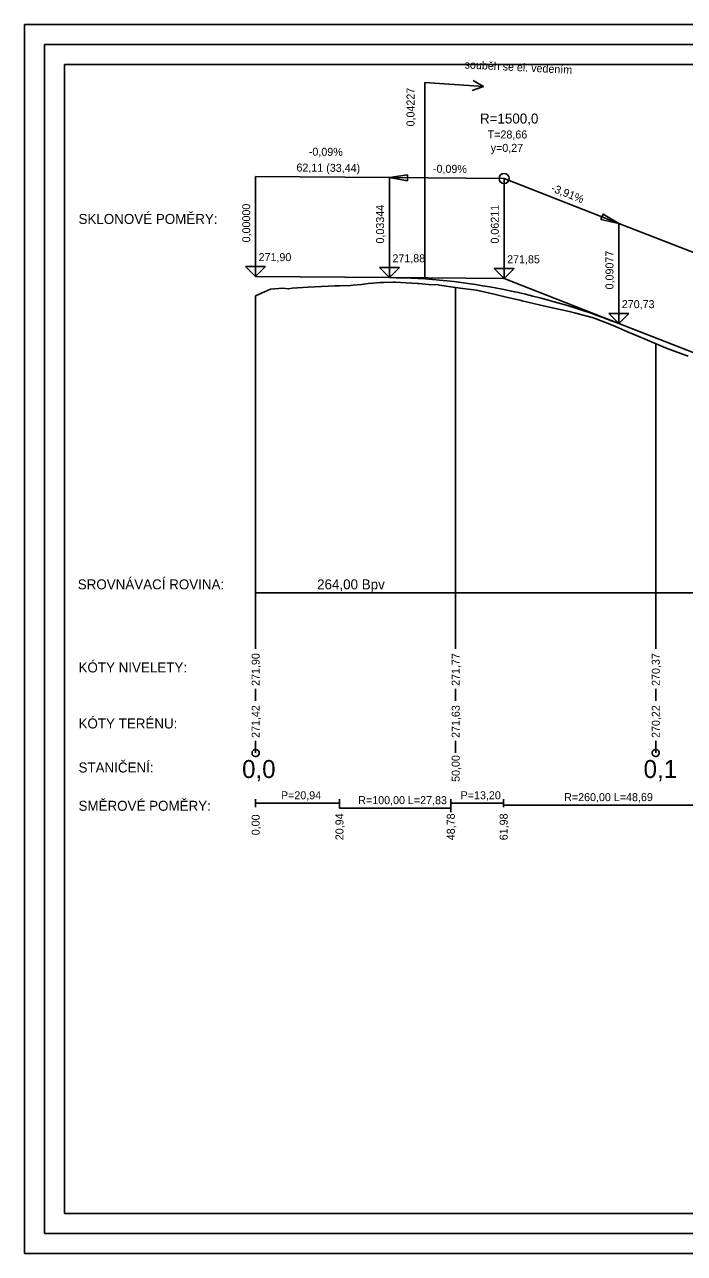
# Model space of a CAD drawing. Extents: x -762531 to -762101, y -1049246 to -1048939.
# Drawn here: x -762531.1 to -762366.2, y -1049246.4 to -1048939.4 of the extents above; entities that cross this region are included whole.
import ezdxf

# ---------------------------------------------------------------- set-up
doc = ezdxf.new("R2010")
doc.units = 0
for name, color, linetype in [('C3D-PROFIL-NIVELETA', 7, 'Continuous'), ('C3D-PROFIL-POPIS', 7, 'Continuous'), ('C3D-PROFIL-POPIS-NIVELETA', 7, 'Continuous'), ('C3D-PROFIL-TEREN', 7, 'Continuous'), ('C3D-ZOBPROF-OSY-NADPIS', 7, 'Continuous'), ('C3D-ZOBPROF-PROUZEK-NAVRH', 7, 'Continuous'), ('C3D-ZOBPROF-PROUZEK-POPIS', 7, 'Continuous'), ('C3D-ZOBPROF-PROUZEK-TEREN', 7, 'Continuous'), ('C3D-ZOBPROF-RASTR-VERHL', 7, 'Continuous'), ('C3D-ZOBPROF-RASTR-VERVEDL', 7, 'Continuous'), ('C3D-ZOBPROF-SROV-ROVINA', 7, 'Continuous'), ('Default', 7, 'Continuous'), ('krizeni_podelnak', 7, 'Continuous'), ('U_formát', 7, 'Continuous'), ('U_rozvržení_rámeček', 7, 'Continuous')]:
    doc.layers.add(name, color=color, linetype=linetype)

# ---------------------------------------------------------------- blocks, each defined once
blk = doc.blocks.new('PP-sipka')
at = {"layer": 'Default'}
for p, q in [((0, 0), (-4, 4)), ((-4, 4), (4, 4)), ((4, 4), (0, 0))]:
    blk.add_line(p, q, dxfattribs=at)
blk = doc.blocks.new('AeccTickCircle')
at = {"layer": 'Default'}
blk.add_circle((0, 0), 0.5, dxfattribs=at)
blk = doc.blocks.new('AeccArwClosedFilled')
at = {"layer": 'Default'}
blk.add_lwpolyline([(0.18, 0.03), (0.18, -0.03), (0, 0)], close=True, dxfattribs=at)
blk = doc.blocks.new('U1096')
at = {"layer": 'Default'}
for p, q in [((-420, 0), (-420, -10)), ((-420, -297), (-420, -287)), ((-420, -297), (-410, -297))]:
    blk.add_line(p, q, dxfattribs=at)
blk.add_lwpolyline([(0, -297), (0, 0), (-420, 0), (-420, -297)], close=True, dxfattribs=at)
at = {"layer": 'U_formát'}
for points in [[(-425, 5), (5, 5), (5, -302), (-425, -302)], [(-5, -292), (-5, -5), (-415, -5), (-415, -292)]]:
    blk.add_lwpolyline(points, close=True, dxfattribs=at)

msp = doc.modelspace()

# ---------------------------------------------------------------- linework, layer by layer
at = {"layer": 'C3D-PROFIL-NIVELETA'}
msp.add_lwpolyline([(-762473.38, -1049002.32), (-762439.93, -1049002.61), (-762438.14, -1049002.63), (-762436.35, -1049002.68), (-762434.56, -1049002.75), (-762432.77, -1049002.84), (-762430.98, -1049002.95), (-762429.19, -1049003.09), (-762427.39, -1049003.24), (-762425.6, -1049003.42), (-762423.81, -1049003.61), (-762422.02, -1049003.83), (-762420.23, -1049004.07), (-762418.44, -1049004.33), (-762416.64, -1049004.62), (-762414.85, -1049004.92), (-762413.06, -1049005.25), (-762411.27, -1049005.59), (-762409.48, -1049005.96), (-762407.69, -1049006.35), (-762405.9, -1049006.76), (-762404.1, -1049007.2), (-762402.31, -1049007.65), (-762400.52, -1049008.13), (-762398.73, -1049008.62), (-762396.94, -1049009.14), (-762395.15, -1049009.68), (-762393.35, -1049010.24), (-762391.56, -1049010.82), (-762389.77, -1049011.43), (-762387.98, -1049012.05), (-762386.19, -1049012.7), (-762384.4, -1049013.37), (-762382.61, -1049014.06), (-762323.08, -1049037.32)], dxfattribs=at)
at = {"layer": 'C3D-PROFIL-POPIS'}
msp.add_line((-762473.38, -1049007.18), (-762473.38, -1049081.36), dxfattribs=at)
at = {"layer": 'C3D-PROFIL-POPIS-NIVELETA'}
for p, q in [((-762473.38, -1049002.32), (-762473.38, -1048977.32)), ((-762473.38, -1048977.32), (-762439.93, -1048977.61)), ((-762439.93, -1049002.61), (-762439.93, -1048977.61)), ((-762439.93, -1048977.61), (-762411.27, -1048977.85)), ((-762439.93, -1049002.61), (-762439.93, -1048977.61)), ((-762411.27, -1049002.85), (-762411.27, -1048977.85)), ((-762411.27, -1048977.85), (-762382.61, -1048989.06)), ((-762382.61, -1049014.06), (-762382.61, -1048989.06)), ((-762382.61, -1049014.06), (-762382.61, -1048989.06)), ((-762382.61, -1048989.06), (-762323.08, -1049012.32)), ((-762411.27, -1049002.85), (-762439.93, -1049002.61)), ((-762411.27, -1049002.85), (-762382.61, -1049014.06))]:
    msp.add_line(p, q, dxfattribs=at)
at = {"layer": 'C3D-PROFIL-TEREN'}
msp.add_lwpolyline([(-762473.38, -1049007.18), (-762469.67, -1049005.49), (-762466.54, -1049005.26), (-762465.13, -1049005.44), (-762464.26, -1049005.27), (-762460.2, -1049004.95), (-762453.6, -1049004.64), (-762452.43, -1049004.62), (-762449.65, -1049004.55), (-762449.01, -1049004.53), (-762446.87, -1049004.29), (-762445.22, -1049004.09), (-762444.08, -1049004), (-762442.15, -1049003.83), (-762441.3, -1049003.8), (-762438.98, -1049003.71), (-762438.52, -1049003.74), (-762435.73, -1049003.93), (-762432.95, -1049004.1), (-762432.66, -1049004.11), (-762430.17, -1049004.29), (-762427.75, -1049004.44), (-762427.38, -1049004.49), (-762424.6, -1049004.9), (-762422.28, -1049005.23), (-762418.17, -1049005.77), (-762413.78, -1049006.75), (-762411.4, -1049007.29), (-762406.97, -1049008.31), (-762406.73, -1049008.37), (-762402.54, -1049009.37), (-762401.39, -1049009.64), (-762398.12, -1049010.38), (-762395.32, -1049011.01), (-762393.69, -1049011.44), (-762389.27, -1049012.59), (-762389.19, -1049012.61), (-762384.84, -1049014.26), (-762383.46, -1049014.79), (-762380.41, -1049016.12), (-762377.57, -1049017.35), (-762375.99, -1049018.02), (-762371.56, -1049019.87), (-762370.51, -1049020.31), (-762367.13, -1049021.57), (-762365.27, -1049022.26)], dxfattribs=at)
at = {"layer": 'C3D-ZOBPROF-PROUZEK-NAVRH'}
for p, q in [((-762473.38, -1049134.93), (-762473.38, -1049132.93)), ((-762473.38, -1049133.93), (-762452.43, -1049133.93)), ((-762452.43, -1049134.93), (-762452.43, -1049132.93)), ((-762452.43, -1049133.93), (-762452.43, -1049135.14)), ((-762452.43, -1049135.14), (-762424.6, -1049135.14)), ((-762424.6, -1049136.14), (-762424.6, -1049132.93)), ((-762424.6, -1049135.14), (-762424.6, -1049133.93)), ((-762424.6, -1049133.93), (-762411.4, -1049133.93)), ((-762411.4, -1049134.93), (-762411.4, -1049132.93)), ((-762411.4, -1049133.93), (-762411.4, -1049134.39)), ((-762411.4, -1049134.39), (-762362.71, -1049134.39))]:
    msp.add_line(p, q, dxfattribs=at)
at = {"layer": 'C3D-ZOBPROF-PROUZEK-POPIS'}
for centre, start, end in [((-762473.38, -1049121.36), 128.6598, 308.6598), ((-762473.38, -1049121.36), 308.6598, 128.6598), ((-762373.38, -1049121.36), 128.6598, 308.6598), ((-762373.38, -1049121.36), 308.6598, 128.6598)]:
    msp.add_arc(centre, 0.89, start, end, dxfattribs=at)
at = {"layer": 'C3D-ZOBPROF-PROUZEK-TEREN'}
for p, q in [((-762473.38, -1049086.36), (-762473.38, -1049081.36)), ((-762423.38, -1049086.36), (-762423.38, -1049081.36)), ((-762373.38, -1049086.36), (-762373.38, -1049081.36)), ((-762473.38, -1049095.36), (-762473.38, -1049086.36)), ((-762423.38, -1049095.36), (-762423.38, -1049086.36)), ((-762373.38, -1049095.36), (-762373.38, -1049086.36)), ((-762473.38, -1049108.36), (-762473.38, -1049105.36)), ((-762423.38, -1049108.36), (-762423.38, -1049105.36)), ((-762373.38, -1049108.36), (-762373.38, -1049105.36)), ((-762473.38, -1049121.36), (-762473.38, -1049118.36)), ((-762423.38, -1049121.36), (-762423.38, -1049118.36)), ((-762373.38, -1049121.36), (-762373.38, -1049118.36))]:
    msp.add_line(p, q, dxfattribs=at)
at = {"layer": 'C3D-ZOBPROF-RASTR-VERHL'}
for p, q in [((-762473.38, -1049081.36), (-762473.38, -1049007.18)), ((-762373.38, -1049081.36), (-762373.38, -1049019.11))]:
    msp.add_line(p, q, dxfattribs=at)
at = {"layer": 'C3D-ZOBPROF-RASTR-VERVEDL'}
msp.add_line((-762423.38, -1049081.36), (-762423.38, -1049005.07), dxfattribs=at)
at = {"layer": 'C3D-ZOBPROF-SROV-ROVINA'}
msp.add_line((-762473.38, -1049081.36), (-762149.73, -1049081.36), dxfattribs=at)
at = {"layer": 'krizeni_podelnak'}
for p, q in [((-762431.11, -1049002.68), (-762431.11, -1048953.89)), ((-762431.11, -1048953.89), (-762416.44, -1048954.84))]:
    msp.add_line(p, q, dxfattribs=at)
msp.add_lwpolyline([(-762419.26, -1048955.86), (-762416.44, -1048954.84), (-762419.04, -1048953.34)], dxfattribs=at)

# ---------------------------------------------------------------- block references
at = {"layer": 'C3D-PROFIL-POPIS-NIVELETA'}
for name, p, xscale, yscale, rotation in [('AeccArwClosedFilled', (-762439.93, -1048977.61), 24.99999999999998, 24.999999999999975, -0.4952226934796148), ('AeccTickCircle', (-762411.27, -1048977.85), 2.5000000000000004, 2.5000000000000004, 90.00000000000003), ('AeccArwClosedFilled', (-762382.61, -1048989.06), 24.999999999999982, 24.999999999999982, 158.65255785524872)]:
    msp.add_blockref(name, p, dxfattribs=dict(at, xscale=xscale, yscale=yscale, rotation=rotation))
at = {"layer": 'C3D-PROFIL-POPIS-NIVELETA', "xscale": 0.625, "yscale": 0.625}
for p in [(-762473.38, -1049002.32), (-762439.93, -1049002.61), (-762411.27, -1049002.85), (-762382.61, -1049014.06)]:
    msp.add_blockref('PP-sipka', p, dxfattribs=at)
at = {"layer": 'U_rozvržení_rámeček'}
msp.add_blockref('U1096', (-762106.11, -1048944.39), dxfattribs=at)

# ---------------------------------------------------------------- texts
at = {"layer": 'C3D-PROFIL-POPIS-NIVELETA'}
for s, height, p in [('R=1500,0', 2.5, (-762417.3, -1048964.11)), ('T=28,66', 2, (-762415.38, -1048967.85)), ('y=0,27', 2, (-762414.62, -1048971.19)), ('271,90', 2, (-762472.63, -1048998.49)), ('271,88', 2, (-762439.18, -1048998.78)), ('271,85', 2, (-762410.52, -1048999.02)), ('270,73', 2, (-762381.86, -1049010.23))]:
    msp.add_text(s, height=height, dxfattribs=at).set_placement(p)
for s, height, rotation, p in [('-0,09%', 2, 359.5048, (-762460.08, -1048972.13)), ('62,11 (33,44)', 2, 359.5048, (-762463.17, -1048976.1)), ('-0,09%', 2, 359.5048, (-762429.06, -1048976.4)), ('-3,91%', 2, 338.6526, (-762399.7, -1048980.98)), ('0,00000', 2, 90, (-762474.71, -1048993.8)), ('0,03344', 2, 90, (-762441.27, -1048994.09)), ('0,06211', 2, 90, (-762412.6, -1048994.1)), ('SKLONOVÉ POMĚRY:', 2.5, 360, (-762517.63, -1048989.2)), ('0,09077', 2, 90, (-762383.94, -1049005.55))]:
    msp.add_text(s, height=height, rotation=rotation, dxfattribs=at).set_placement(p)
at = {"layer": 'C3D-ZOBPROF-OSY-NADPIS'}
msp.add_text('SROVNÁVACÍ ROVINA:                         264,00 Bpv', height=2.5, dxfattribs=at).set_placement((-762517.82, -1049080.49))
at = {"layer": 'C3D-ZOBPROF-PROUZEK-NAVRH'}
for s, height, p in [('P=20,94', 2, (-762467.04, -1049132.93)), ('R=100,00 L=27,83', 2, (-762447.72, -1049134.15)), ('P=13,20', 2, (-762422.14, -1049132.93)), ('R=260,00 L=48,69', 2, (-762396.26, -1049133.4)), ('SMĚROVÉ POMĚRY:', 2.5, (-762517.63, -1049135.81))]:
    msp.add_text(s, height=height, dxfattribs=at).set_placement(p)
for s, p in [('0,00', (-762472.37, -1049141.92)), ('20,94', (-762451.42, -1049143.16)), ('48,78', (-762423.59, -1049143.17)), ('61,98', (-762410.39, -1049143.17))]:
    msp.add_text(s, height=2, rotation=90, dxfattribs=at).set_placement(p)
at = {"layer": 'C3D-ZOBPROF-PROUZEK-POPIS'}
for s, p in [('0,0', (-762476.75, -1049127.62)), ('0,1', (-762376.41, -1049127.62))]:
    msp.add_text(s, height=4.5, dxfattribs=at).set_placement(p)
at = {"layer": 'C3D-ZOBPROF-PROUZEK-TEREN'}
for s, p in [('KÓTY NIVELETY:', (-762517.63, -1049101.24)), ('KÓTY TERÉNU:', (-762517.63, -1049115.24)), ('STANIČENÍ:', (-762517.63, -1049126.24))]:
    msp.add_text(s, height=2.5, dxfattribs=at).set_placement(p)
for s, p in [('271,90', (-762472.37, -1049104.61)), ('271,77', (-762422.37, -1049104.61)), ('270,37', (-762372.37, -1049104.61)), ('271,42', (-762472.37, -1049117.61)), ('271,63', (-762422.37, -1049117.61)), ('270,22', (-762372.37, -1049117.61)), ('50,00', (-762422.37, -1049128.59))]:
    msp.add_text(s, height=2, rotation=90, dxfattribs=at).set_placement(p)
at = {"layer": 'krizeni_podelnak'}
for s, rotation, p in [('souběh se el. vedením', 357.0888, (-762421.18, -1048950.34)), ('0,04227', 90, (-762433.66, -1048964.84))]:
    msp.add_text(s, height=2, rotation=rotation, dxfattribs=at).set_placement(p)

doc.saveas('drawing.dxf')
